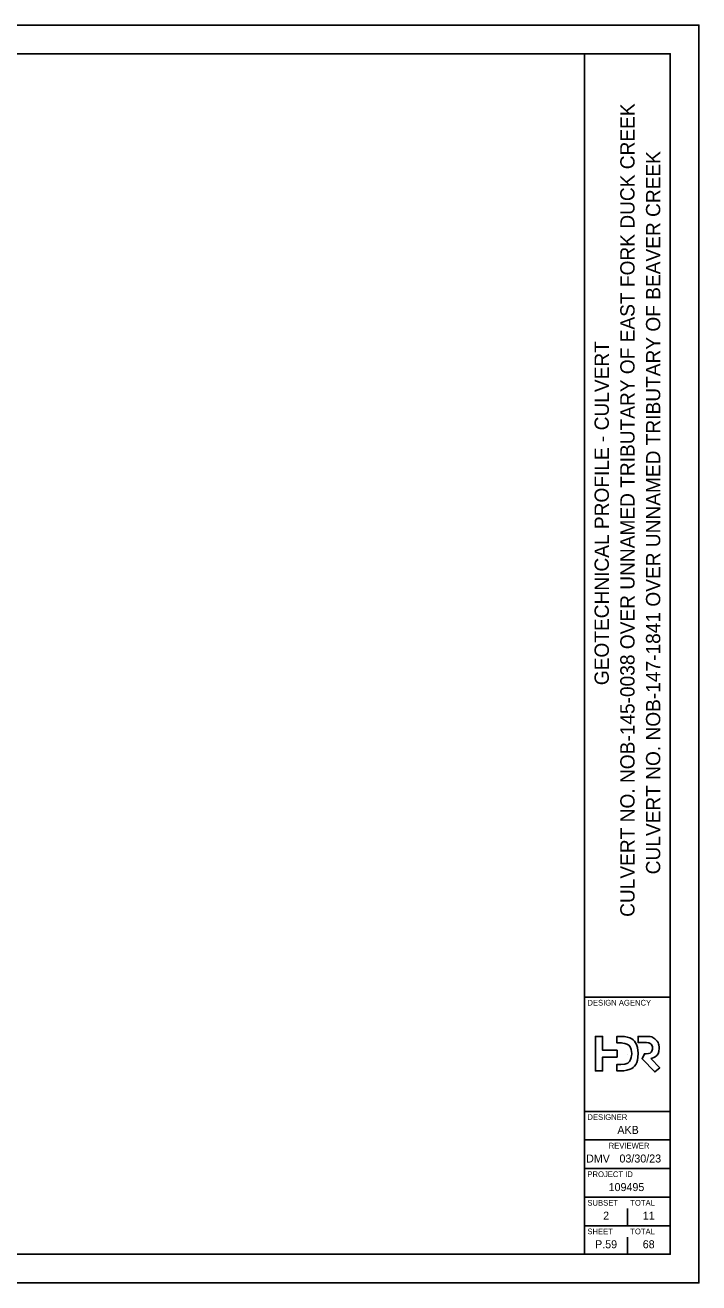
# Model space of a CAD drawing. Extents: x 0 to 34, y 0 to 22.
# Drawn here: x 22.21 to 34, y 0 to 22 of the extents above; entities that cross this region are included whole.
import ezdxf

# ---------------------------------------------------------------- set-up
doc = ezdxf.new("R2010")
doc.units = 0
for name, color, linetype in [('SH_Border', 7, 'Continuous'), ('SH_Cut_Line', 7, 'Continuous'), ('SH_Data', 7, 'Continuous')]:
    doc.layers.add(name, color=color, linetype=linetype)

msp = doc.modelspace()

# ---------------------------------------------------------------- linework, layer by layer
at = {"layer": 'SH_Border'}
for p, q in [((32, 0.5), (32, 21.5)), ((32, 5), (33.5, 5)), ((32, 3), (33.5, 3)), ((32, 2.5), (33.5, 2.5)), ((32, 2), (33.5, 2)), ((32, 1.5), (33.5, 1.5)), ((32, 1), (33.5, 1))]:
    msp.add_line(p, q, dxfattribs=at)
msp.add_lwpolyline([(1.5, 21.5), (33.5, 21.5), (33.5, 0.5), (1.5, 0.5)], close=True, dxfattribs=at)
at = {"layer": 'SH_Cut_Line'}
msp.add_lwpolyline([(0, 0), (34, 0), (34, 22), (0, 22)], close=True, dxfattribs=at)
at = {"layer": 'SH_Data'}
for p, q in [((32.75, 4), (32.75, 4)), ((32.75, 1), (32.75, 1.3)), ((32.375, 0.675), (32.375, 0.675)), ((32.75, 0.5), (32.75, 0.8))]:
    msp.add_line(p, q, dxfattribs=at)
msp.add_lwpolyline([(32.568, 4.069), (32.314, 4.069), (32.314, 4.311), (32.191, 4.311), (32.191, 3.707), (32.314, 3.707), (32.314, 3.948), (32.568, 3.948)], close=True, dxfattribs=at)
for points in [[(32.636, 4.311), (32.565, 4.311), (32.565, 4.197), (32.636, 4.197)], [(33.066, 4.311), (32.938, 4.311), (32.938, 4.202), (33.074, 4.202)], [(32.938, 4.009), (32.938, 4.009), (32.938, 4.009), (32.938, 4.009), (32.938, 4.009)], [(33.08, 4.008), (33.046, 4.008), (33.006, 3.921), (33.229, 3.69), (33.316, 3.763), (33.158, 3.922)], [(32.636, 3.82), (32.565, 3.82), (32.565, 3.707), (32.636, 3.707)]]:
    msp.add_lwpolyline(points, dxfattribs=at)
for points in [[(32.938, 4.009), (32.938, 4.009), (32.938, 4.184), (32.811, 4.311), (32.636, 4.311)], [(32.636, 4.197), (32.636, 4.197), (32.747, 4.197), (32.825, 4.12), (32.825, 4.009)], [(33.242, 4.256), (33.242, 4.256), (33.195, 4.3), (33.144, 4.311), (33.066, 4.311)], [(33.074, 4.202), (33.074, 4.202), (33.115, 4.202), (33.143, 4.193), (33.163, 4.174)], [(33.305, 4.103), (33.305, 4.103), (33.305, 4.166), (33.287, 4.214), (33.242, 4.256)], [(32.825, 4.009), (32.825, 4.009), (32.825, 3.898), (32.747, 3.82), (32.636, 3.82)], [(32.636, 3.707), (32.636, 3.707), (32.811, 3.707), (32.938, 3.834), (32.938, 4.009)], [(33.191, 4.105), (33.191, 4.105), (33.191, 4.044), (33.139, 4.008), (33.08, 4.008)], [(33.158, 3.922), (33.158, 3.922), (33.245, 3.939), (33.305, 4.019), (33.305, 4.103)], [(33.163, 4.174), (33.163, 4.174), (33.182, 4.156), (33.191, 4.132), (33.191, 4.105)]]:
    msp.add_open_spline(points, degree=3, dxfattribs=at)

# ---------------------------------------------------------------- texts
for s, p in [('CULVERT NO. NOB-145-0038 OVER UNNAMED TRIBUTARY OF EAST FORK DUCK CREEK', (32.875, 6.402)), ('CULVERT NO. NOB-147-1841 OVER UNNAMED TRIBUTARY OF BEAVER CREEK', (33.325, 7.146)), ('GEOTECHNICAL PROFILE - CULVERT', (32.425, 10.454))]:
    msp.add_text(s, height=0.25, rotation=90, dxfattribs=at).set_placement(p)
for s, height, p in [('DESIGN AGENCY', 0.1, (32.05, 4.85)), ('DESIGNER', 0.1, (32.05, 2.85)), ('AKB', 0.14, (32.574, 2.605)), ('REVIEWER', 0.1, (32.422, 2.35)), ('DMV', 0.14, (32.027, 2.105)), ('03/30/23', 0.14, (32.611, 2.105)), ('PROJECT ID', 0.1, (32.05, 1.85)), ('109495', 0.14, (32.421, 1.605)), ('SUBSET', 0.1, (32.05, 1.35)), ('TOTAL', 0.1, (32.8, 1.35)), ('2', 0.14, (32.325, 1.105)), ('11', 0.14, (33.019, 1.105)), ('SHEET', 0.1, (32.05, 0.85)), ('TOTAL', 0.1, (32.8, 0.85)), ('P.59', 0.14, (32.184, 0.605)), ('68', 0.14, (33.018, 0.605))]:
    msp.add_text(s, height=height, dxfattribs=at).set_placement(p)

doc.saveas('drawing.dxf')
